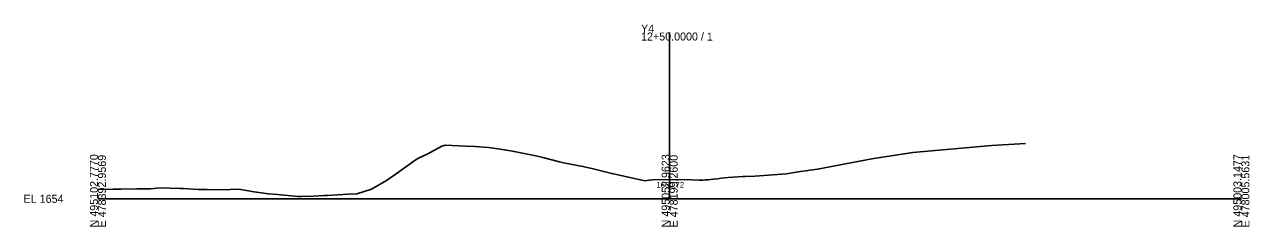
# Model space of a CAD drawing. Extents: x -26 to 403, y -10 to 5108.
# Drawn here: x -25.7 to 402.8, y 2490.3 to 2561 of the extents above; entities that cross this region are included whole.
import ezdxf

# ---------------------------------------------------------------- set-up
doc = ezdxf.new("R2010")
doc.units = 0
for name, color, linetype in [('Exist Cross Section Cell', 7, 'Continuous'), ('Exist XS Center Line Elevation Label', 7, 'Continuous'), ('Exist XS Ground Line', 7, 'Continuous')]:
    doc.layers.add(name, color=color, linetype=linetype)

msp = doc.modelspace()

# ---------------------------------------------------------------- linework, layer by layer
at = {"layer": 'Exist Cross Section Cell'}
for p, q in [((200, 2500), (200, 2558.21)), ((0, 2500), (200, 2500)), ((200, 2500), (400, 2500))]:
    msp.add_line(p, q, dxfattribs=at)
at = {"layer": 'Exist XS Ground Line'}
msp.add_lwpolyline([(0, 2503.21), (5.34, 2503.42), (8, 2503.39), (13.55, 2503.51), (18.33, 2503.53), (21.77, 2503.89), (28.66, 2503.59), (29.98, 2503.58), (35.14, 2503.31), (38.2, 2503.21), (38.98, 2503.16), (46.41, 2503.25), (49.31, 2503.35), (54.63, 2502.39), (59.64, 2501.69), (62.84, 2501.54), (69.96, 2500.83), (71.06, 2500.85), (75.3, 2500.9), (79.27, 2501.12), (80.29, 2501.12), (87.49, 2501.65), (90.62, 2501.75), (95.7, 2503.38), (100.95, 2506.39), (103.92, 2508.53), (111.27, 2513.74), (112.13, 2514.19), (115.46, 2515.8), (120.34, 2518.4), (121.6, 2518.79), (128.56, 2518.44), (131.93, 2518.33), (136.77, 2517.92), (142.26, 2517.15), (144.99, 2516.68), (152.58, 2515.2), (153.2, 2515.07), (155.61, 2514.43), (161.42, 2512.94), (162.91, 2512.61), (169.63, 2511.34), (173.24, 2510.5), (179.28, 2508.93), (191.34, 2506.32), (192.81, 2506.57), (194, 2506.69), (200, 2506.72), (207.69, 2506.64), (210.3, 2506.58), (211.61, 2506.57), (212.59, 2506.6), (213.52, 2506.65), (214.33, 2506.75), (215.29, 2506.85), (216.72, 2507.02), (217.99, 2507.18), (220.48, 2507.43), (225.65, 2507.76), (226.44, 2507.82), (229.78, 2507.97), (240.83, 2508.72), (245.01, 2509.44), (251.76, 2510.39), (270.74, 2514.05), (285.06, 2516.19), (312.6, 2518.7), (324.48, 2519.4)], dxfattribs=at)

# ---------------------------------------------------------------- texts
at = {"layer": 'Exist Cross Section Cell'}
for s, p in [('Y4', (190, 2558.21)), ('12+50.0000 / 1', (190, 2555.41)), ('EL 1654', (-26, 2498.6))]:
    msp.add_text(s, height=2.8, dxfattribs=at).set_placement(p)
for s, p in [('N 495102.7770', (0, 2490)), ('E 478392.9569', (2.8, 2490)), ('N 495052.9623', (200, 2490)), ('E 478199.2600', (202.8, 2490)), ('N 495003.1477', (400, 2490)), ('E 478005.5631', (402.8, 2490))]:
    msp.add_text(s, height=2.8, rotation=90, dxfattribs=at).set_placement(p)
at = {"layer": 'Exist XS Center Line Elevation Label'}
msp.add_text('1660.72', height=2, dxfattribs=at).set_placement((195.38, 2503.88))

doc.saveas('drawing.dxf')
